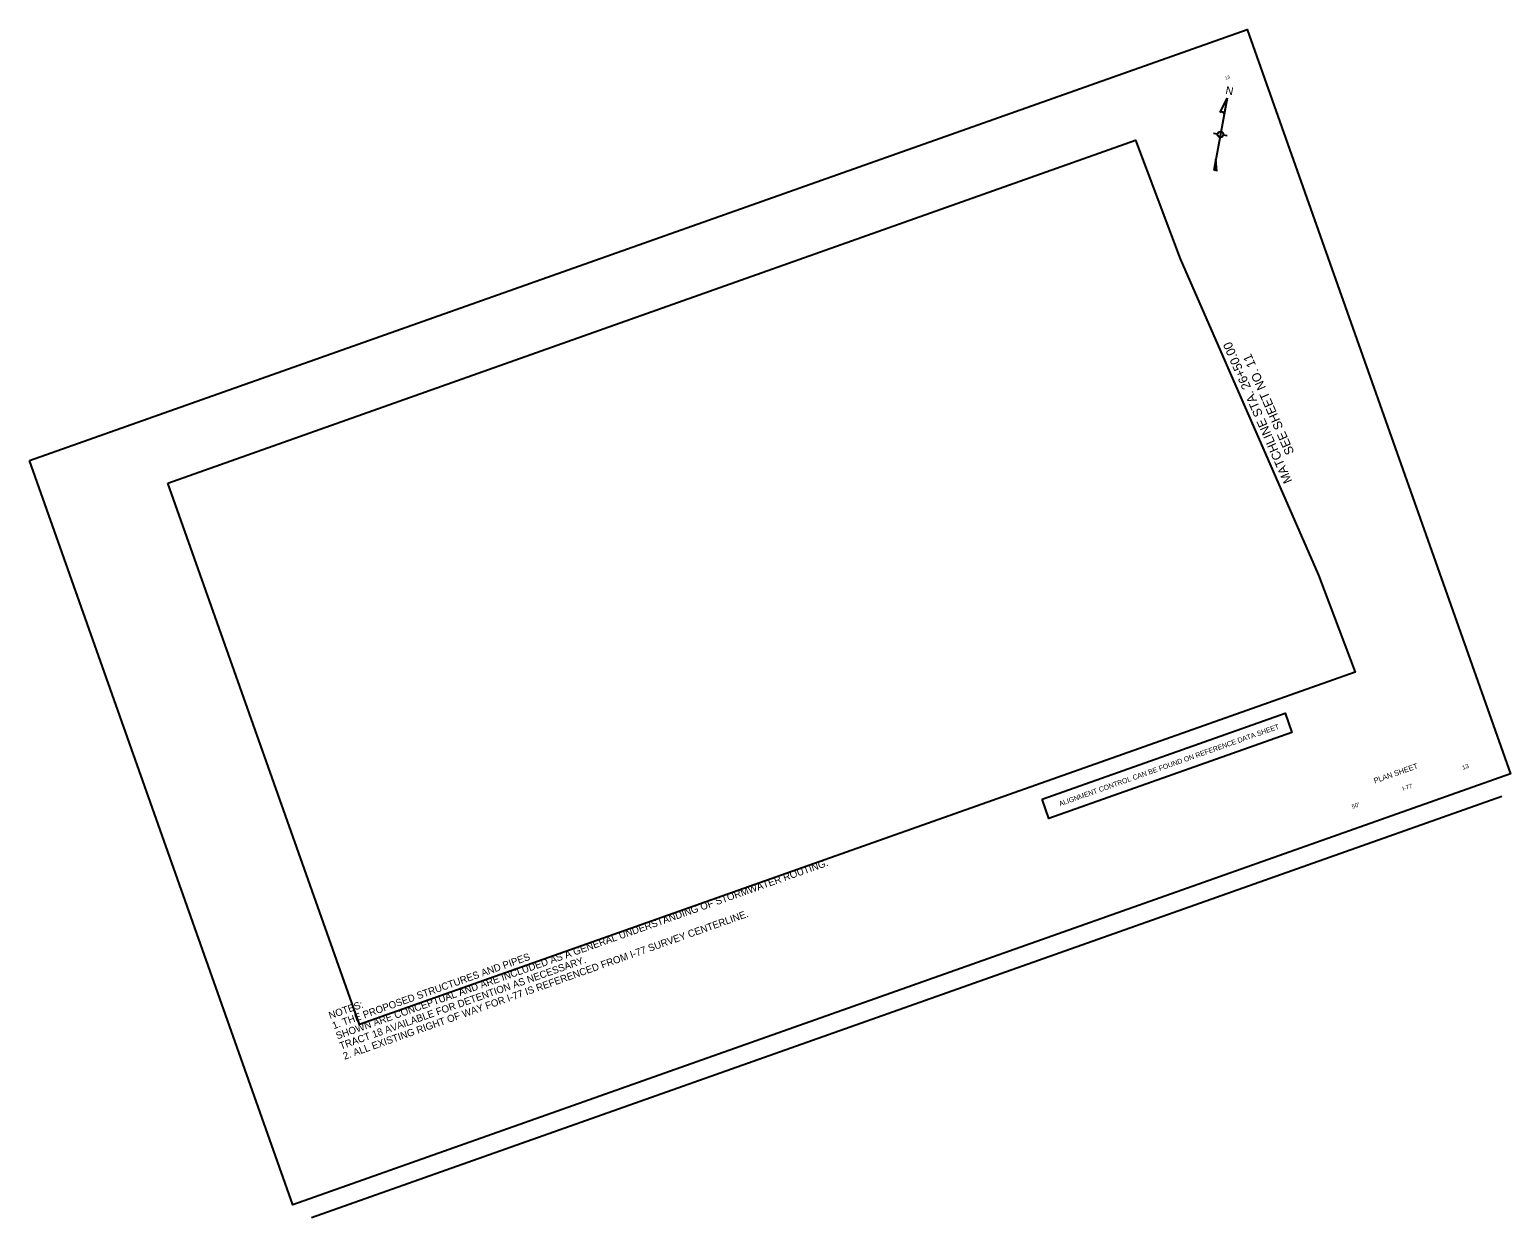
# Model space of a CAD drawing. Extents: x 2003337 to 2005401, y 1135705 to 1137360.
import ezdxf

# ---------------------------------------------------------------- set-up
doc = ezdxf.new("R2010")
doc.units = 0
for name, color, linetype in [('North Arrow', 7, 'Continuous'), ('RD_SHT_IplotShp', 7, 'Continuous'), ('RD_SHT_MatchLine', 7, 'Continuous'), ('RD_SHT_Misc1', 7, 'Continuous'), ('RD_SHT_ShtClip', 7, 'Continuous'), ('RD_SHT_TX', 7, 'Continuous')]:
    doc.layers.add(name, color=color, linetype=linetype)

msp = doc.modelspace()

# ---------------------------------------------------------------- linework, layer by layer
at = {"layer": 'North Arrow'}
for p, q in [((2005006.1, 1137264.4), (2004987.3, 1137163.9)), ((2004996.4, 1137244.8), (2005006.1, 1137264.4)), ((2005006.1, 1137264.4), (2005002, 1137242.6)), ((2004987.2, 1137215.9), (2004992.8, 1137214.9)), ((2005000.7, 1137213.4), (2005006.3, 1137212.4)), ((2004990.2, 1137179.5), (2004987.3, 1137163.9)), ((2004991.8, 1137162.8), (2004990.2, 1137179.5))]:
    msp.add_line(p, q, dxfattribs=at)
msp.add_circle((2004996.7, 1137214.2), 4.02, dxfattribs=at)
for centre, radius, start, end in [((2004998.5, 1137241.9), 3.59, 11.8077, 125.5757), ((2004989, 1137161.1), 3.3, 32.7767, 119.9977)]:
    msp.add_arc(centre, radius, start, end, dxfattribs=at)
at = {"layer": 'RD_SHT_IplotShp'}
msp.add_lwpolyline([(2003337, 1136759.8), (2005034, 1137360.1), (2005400.8, 1136323.1), (2003703.9, 1135722.8)], close=True, dxfattribs=at)
at = {"layer": 'RD_SHT_MatchLine'}
msp.add_line((2004940.5, 1137040.7), (2005133.6, 1136600.2), dxfattribs=at)
at = {"layer": 'RD_SHT_ShtClip'}
msp.add_lwpolyline([(2003529.8, 1136728.4), (2004878.4, 1137206.1), (2004940.5, 1137040.7), (2005133.6, 1136600.2), (2005184.4, 1136465.1), (2003796.6, 1135974.2)], close=True, dxfattribs=at)
at = {"layer": 'RD_SHT_TX'}
msp.add_line((2003729.8, 1135705.4), (2005389, 1136292.4), dxfattribs=at)
msp.add_lwpolyline([(2004748.3, 1136288.1), (2005086.9, 1136407.9), (2005096.3, 1136381.1), (2004757.7, 1136261.3)], close=True, dxfattribs=at)

# ---------------------------------------------------------------- texts
at = {"layer": 'North Arrow'}
msp.add_text('N', height=11.1, rotation=349.437, dxfattribs=at).set_placement((2005003.1, 1137270.6))
at = {"layer": 'RD_SHT_MatchLine'}
for s, p in [('MATCHLINE STA. 26+50.00', (2005096.9, 1136731.1)), ('SEE SHEET NO. 11', (2005099.9, 1136771))]:
    msp.add_text(s, height=12.5, rotation=113.6727, dxfattribs=at).set_placement(p)
at = {"layer": 'RD_SHT_Misc1'}
for s, p in [('SHOWN ARE CONCEPTUAL AND ARE INCLUDED AS A GENERAL UNDERSTANDING OF STORMWATER ROUTING.  ', (2003765.9, 1135953.2)), ('2. ALL EXISTING RIGHT OF WAY FOR I-77 IS REFERENCED FROM I-77 SURVEY CENTERLINE.', (2003775.9, 1135924.9)), ('1. THE PROPOSED STRUCTURES AND PIPES ', (2003760.9, 1135967.4)), ('TRACT 18 AVAILABLE FOR DETENTION AS NECESSARY. ', (2003770.9, 1135939.1)), ('NOTES:', (2003755.9, 1135981.5))]:
    msp.add_text(s, height=10, rotation=19.4825, dxfattribs=at).set_placement(p)
at = {"layer": 'RD_SHT_TX'}
for s, height, rotation, p in [('13', 4.5, 19.4825, (2005003.9, 1137290.1)), ('ALIGNMENT CONTROL CAN BE FOUND ON REFERENCE DATA SHEET', 7, 19.482, (2004772.9, 1136278)), ('PLAN SHEET', 7.5, 19.4825, (2005211.9, 1136309.8)), ('13', 6, 19.4825, (2005334.8, 1136328.9)), ('I-77', 6, 19.4825, (2005251.5, 1136299.4)), ("50'", 6, 19.4825, (2005180.9, 1136274.5))]:
    msp.add_text(s, height=height, rotation=rotation, dxfattribs=at).set_placement(p)

doc.saveas('drawing.dxf')
